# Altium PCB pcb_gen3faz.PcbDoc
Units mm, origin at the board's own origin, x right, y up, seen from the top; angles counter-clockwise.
Board outline 69.09 x 22.1 mm, 2 copper layers (Top Layer, Bottom Layer); 24 components, 18 nets, 67 pads, 0 vias.
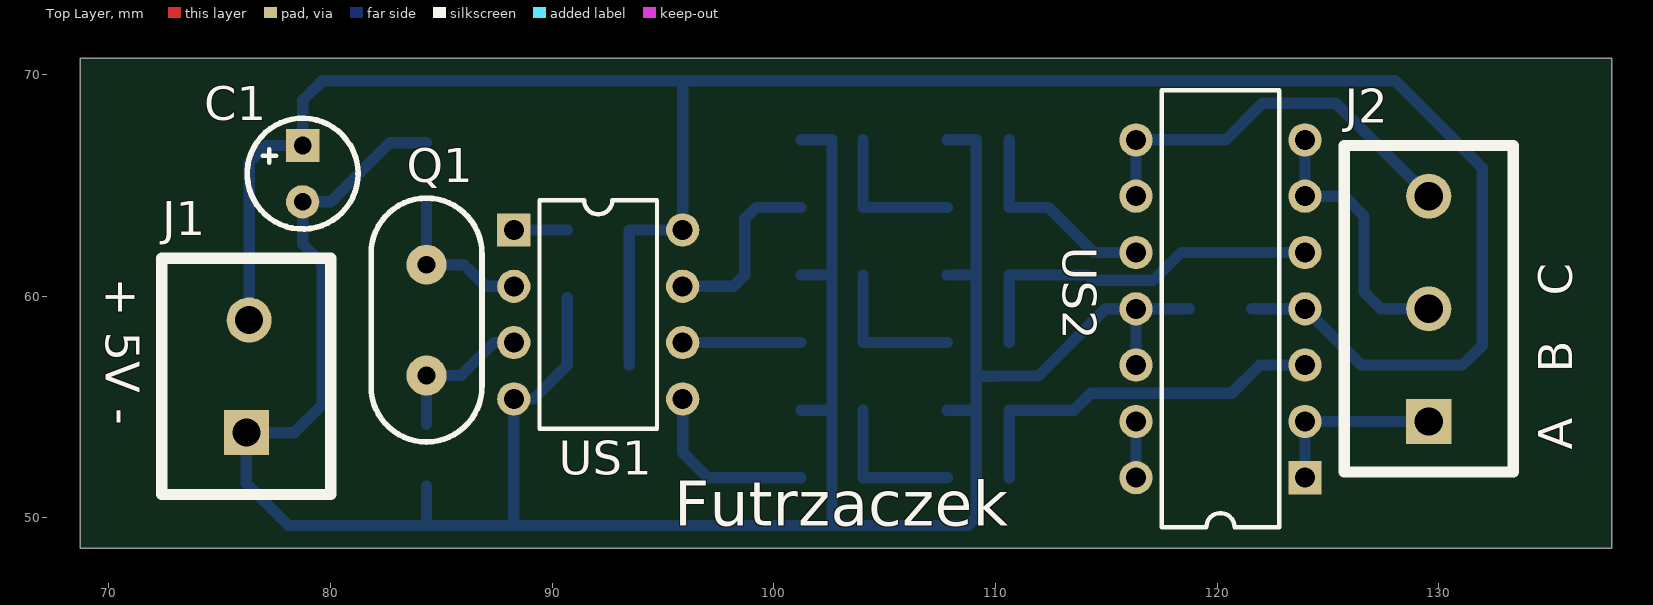
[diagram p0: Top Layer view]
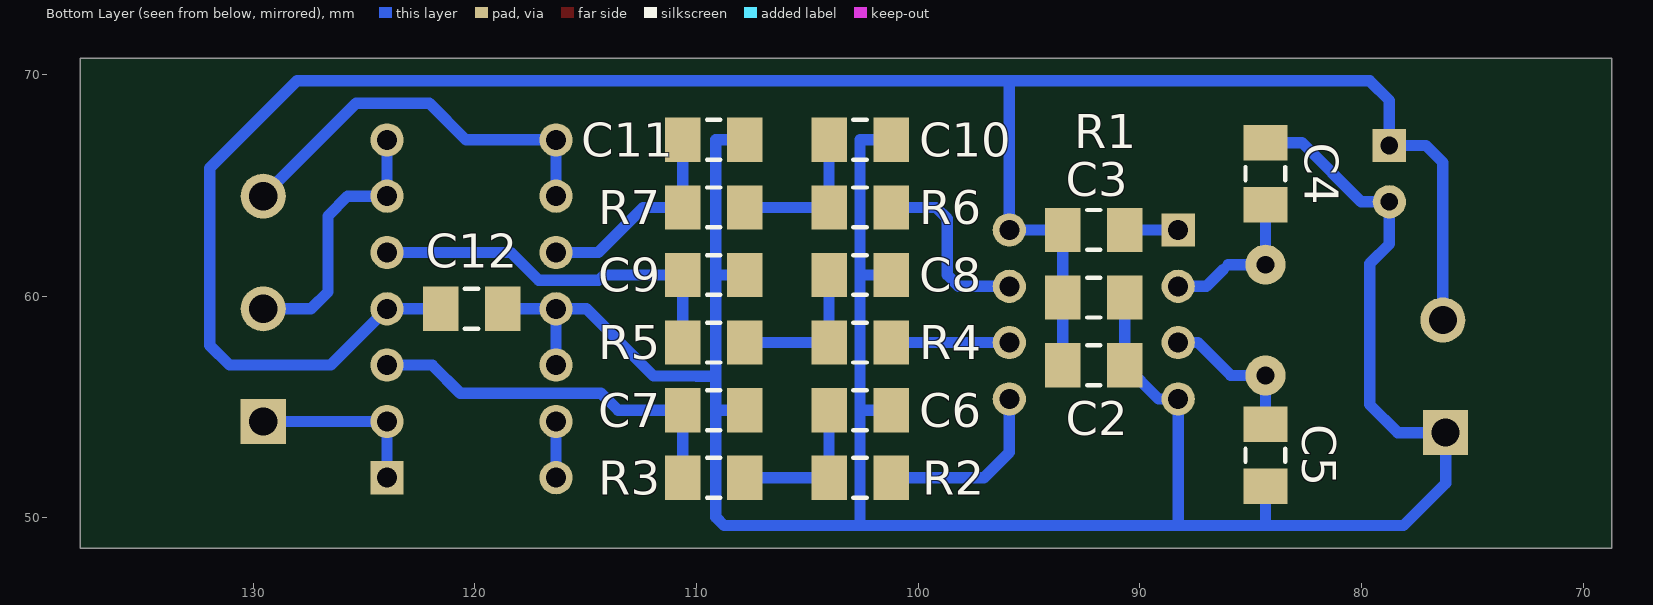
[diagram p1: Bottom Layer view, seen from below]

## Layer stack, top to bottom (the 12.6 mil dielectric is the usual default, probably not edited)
Top Layer: signal copper 0.0356
Dielectric: dielectric 0.32, FR-4, Dk 4.8
Bottom Layer: signal copper 0.0356

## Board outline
68.707,48.641 68.707,70.739 137.795,70.739 137.795,48.641

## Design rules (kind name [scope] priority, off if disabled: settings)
Clearance [All] p1: gap=0.254
PolygonConnect [All] p1: connectstyle=Relief reliefconductorwidth=0.254 reliefentries=4 polygonreliefangle="90 Angle"
RoutingVias [All] p1: holewidth=0.8 width=1.5 viastyle="Through Hole" minholewidth=0.8 minwidth=1.5 maxholewidth=0.8 maxwidth=1.5
SilkscreenOverComponentPads [All] p1: minsilkscreentomaskgap=0.254
SolderMaskExpansion [All] p1: expansion=0.102
Width [All] p1: maxlimit=2.54 minlimit=0.254 preferedwidth=0.508
27 further rules are at their usual default settings.

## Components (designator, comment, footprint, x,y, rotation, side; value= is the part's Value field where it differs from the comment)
C1 "100u/16V" "2,5/5mm elektrolit" 78.74,65.532 r270 top
C2 "470p" MELF-1206 92.075,56.896 r0 bottom
C3 "100n" MELF-1206 92.075,59.944 r0 bottom
C4 "18p" MELF-1206 84.328,65.532 r270 bottom
C5 "18p" MELF-1206 84.328,52.832 r90 bottom
C6 "100n" MELF-1206 102.616,54.864 r0 bottom
C7 "100n" MELF-1206 109.22,54.864 r0 bottom
C8 "100n" MELF-1206 102.616,60.96 r0 bottom
C9 "100n" MELF-1206 109.22,60.96 r0 bottom
C10 "100n" MELF-1206 102.616,67.056 r0 bottom
C11 "100n" MELF-1206 109.22,67.056 r0 bottom
C12 "100n" MELF-1206 120.142,59.436 r0 bottom
J1 "ARK2" "ARK2 5mm" 76.2,56.388 r90 top
J2 "ARK3" "ARK3 5mm" 129.54,59.436 r90 top
Q1 "16MHz" "kwarc 5mm" 84.328,58.928 r90 top
R1 "4,7k" MELF-1206 92.075,62.992 r0 bottom
R2 "4,7k" MELF-1206 102.616,51.816 r180 bottom
R3 "33k" MELF-1206 109.22,51.816 r180 bottom
R4 "4,7k" MELF-1206 102.616,57.912 r180 bottom
R5 "33k" MELF-1206 109.22,57.912 r180 bottom
R6 "4,7k" MELF-1206 102.616,64.008 r180 bottom
R7 "33k" MELF-1206 109.22,64.008 r180 bottom
US1 "ATtiny25" 8P3 92.075,59.182 r270 top
US2 "LM324" N014 120.142,59.436 r90 top

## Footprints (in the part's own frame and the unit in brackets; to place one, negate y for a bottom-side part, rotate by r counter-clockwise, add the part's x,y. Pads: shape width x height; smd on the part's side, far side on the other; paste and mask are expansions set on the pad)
"2,5/5mm elektrolit" [mm]
  rect 1.5x1.5 hole 0.8: 1(-1.27,0)
  round 1.5 hole 0.8: 2(1.27,0)
  silkscreen extent -2.5,-2.5 2.5,2.5, body extent -2.51,-2.51 2.51,2.51
8P3 [mm] "DIP; 8 Leads; Row Spacing 7.62 mm; Pitch 2.54 mm"
  rect 1.5x1.5 hole 0.9: 1(-3.81,-3.81)
  round 1.5 hole 0.9: 2(-1.27,-3.81) 3(1.27,-3.81) 4(3.81,-3.81) 5(3.81,3.81) 6(1.27,3.81) 7(-1.27,3.81) 8(-3.81,3.81)
  silkscreen extent -5.15,-2.65 5.15,2.65
"ARK2 5mm" [mil]
  rect 80x80 hole 50: 1(-100,0)
  round 80 hole 50: 2(100,-5)
  silkscreen extent -210,-150 210,150, body extent -220,-160 220,160, height 394
"ARK3 5mm" [mil]
  rect 80x80 hole 50: 1(-200,0)
  round 80 hole 50: 2(0,0) 3(200,0)
  silkscreen extent -290,-150 290,150, body extent -300,-160 300,160, height 394
"kwarc 5mm" [mm]
  round 1.8 hole 0.8: 1(-2.5,0) 2(2.5,0)
  silkscreen extent -5.5,-2.5 5.5,2.5
MELF-1206 [mm] "Metal Electrode Face (MELF) Resistor; Body 3.2 x 1.8 mm (LxDia)"
  rect 1.6x2 smd: 1(-1.4,0) 2(1.4,0)
  silkscreen extent -0.3,-0.9 0.3,0.9, body extent -2.3,-1.1 2.3,1.1, height 1.85
N014 [mm] "DIP; 14 Leads; Row Spacing 7.62 mm; Pitch 2.54 mm"
  rect 1.5x1.5 hole 0.9: 1(-7.62,-3.81)
  round 1.5 hole 0.9: 2(-5.08,-3.81) 3(-2.54,-3.81) 4(0,-3.81) 5(2.54,-3.81) 6(5.08,-3.81) 7(7.62,-3.81) 8(7.62,3.81) 9(5.08,3.81) 10(2.54,3.81) 11(0,3.81) 12(-2.54,3.81) 13(-5.08,3.81) 14(-7.62,3.81)
  silkscreen extent -9.85,-2.65 9.85,2.65

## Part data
C1: library part "kond biegunowy", "Polarized Capacitor"
C2 C3 C4 C5 C6 C7 C8 C9 C10 C11 C12: library part kondensator
Q1: library part kwarc
R1 R2 R3 R4 R5 R6 R7: library part rezystor
US1: library part ATtiny12V-1PI, "8-Bit AVR Microcontroller with 1K Byte of Flash Memory"
US2: library part LM324AN, "Quadruple Operational Amplifier"

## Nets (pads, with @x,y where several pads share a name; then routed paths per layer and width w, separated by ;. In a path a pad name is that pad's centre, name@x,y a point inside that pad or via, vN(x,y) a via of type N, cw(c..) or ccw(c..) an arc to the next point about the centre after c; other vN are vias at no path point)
+5V: C1.1 C2.2 C3.2 C12.2 J1.2 R1.2 US1.8 US2.4 | length 102.7
  Bottom Layer w0.508: J1.2 76.327,66.04 77.089,66.802 C1.1 78.74,68.834 79.629,69.723 95.885,69.723 ; C2.2 C3.2 R1.2 US1.8 ; US1.8@95.377,62.992 US1.8 ; C12.2 US2.4 126.492,56.896 131.064,56.896 131.953,57.785 131.953,65.786 128.016,69.723 95.885,69.723 ; US1.8 95.885,69.723
GND: C1.2 C2.1 C3.1 C4.1 C5.1 C6.1 C7.1 C8.1 C9.1 C10.1 C11.1 C12.1 J1.1 US1.4 US2.11 US2.12 | length 126.6
  Bottom Layer w0.508: 84.328,49.784 C5.1 ; C4.1 82.68,66.932 80.01,64.262 C1.2 78.74,62.357 79.629,61.468 79.629,55.118 78.359,53.848 J1.1 76.2,51.562 78.105,49.657 88.265,49.657 ; C3.1 C2.1 89.151,55.372 US1.4 88.265,49.657 ; C6.1 102.616,54.864 ; C8.1 102.616,60.96 ; C10.1 102.616,67.056 102.616,60.96 ; 102.616,49.657 101.6,49.657 ; 102.616,49.784 102.616,54.864 ; C7.1 109.128,54.864 ; C9.1 109.128,60.96 ; C11.1 109.128,67.056 109.128,60.96 ; US2.12 US2.11 ; C12.1 US2.11 ; 88.265,49.657 101.6,49.657 ; 101.6,49.657 108.747,49.657 109.128,50.038 109.128,54.864 ; 102.616,54.864 102.616,60.96 ; 109.128,54.864 109.128,56.388 ; 109.128,56.388 109.128,60.96 ; 109.128,56.388 109.982,56.388 109.998,56.404 111.928,56.404 114.96,59.436 US2.11
NetC6_2: C6.2 R2.1 R3.2 | length 6.9
  Bottom Layer w0.508: C6.2 R2.1 R3.2
NetC7_2: C7.2 R3.1 US2.3 | length 17.2
  Bottom Layer w0.508: R3.1 C7.2 113.538,54.864 114.3,55.626 120.65,55.626 121.92,56.896 US2.3
NetC8_2: C8.2 R4.1 R5.2 | length 6.9
  Bottom Layer w0.508: C8.2 R4.1 R5.2
NetC9_2: C9.2 R5.1 US2.5 | length 17
  Bottom Layer w0.508: R5.1 C9.2 114.173,60.96 114.415,60.718 117.106,60.718 117.348,60.96 118.364,61.976 US2.5
NetC10_2: C10.2 R6.1 R7.2 | length 6.9
  Bottom Layer w0.508: C10.2 R6.1 R7.2
NetC11_2: C11.2 R7.1 US2.10 | length 9.6
  Bottom Layer w0.508: C11.2 R7.1 112.395,64.008 114.427,61.976 US2.10
NetJ2_1: J2.1 US2.1 US2.2 | length 8.1
  Bottom Layer w0.508: US2.1 US2.2 J2.1
NetJ2_2: J2.2 US2.6 US2.7 | length 12.2
  Bottom Layer w0.508: US2.7 US2.6 125.73,64.516 126.619,63.627 126.619,60.198 127.381,59.436 J2.2
NetJ2_3: J2.3 US2.8 US2.9 | length 18.2
  Bottom Layer w0.508: US2.9 US2.8 120.396,67.056 122.047,68.707 125.349,68.707 J2.3
NetR1_1: R1.1 US1.1 | length 2.4
  Bottom Layer w0.508: US1.1 R1.1
NetUS2_13: US2.13 US2.14 | length 2.5
  Bottom Layer w0.508: US2.14 US2.13
PWM1: R2.2 US1.5 | length 8.2
  Bottom Layer w0.508: US1.5 95.885,52.959 97.028,51.816 R2.2
PWM2: R4.2 US1.6 | length 5.3
  Bottom Layer w0.508: US1.6 R4.2
PWM3: R6.2 US1.7 | length 8.3
  Bottom Layer w0.508: US1.7 98.171,60.452 98.679,60.96 98.679,63.5 99.187,64.008 R6.2
XTAL1: C4.2 Q1.2 US1.2 | length 6.7
  Bottom Layer w0.508: C4.2 Q1.2 86.019,61.428 ; 86.233,61.214 86.995,60.452 US1.2
XTAL2: C5.2 Q1.1 US1.3 | length 6.7
  Bottom Layer w0.508: C5.2 Q1.1 85.892,56.428 87.376,57.912 US1.3

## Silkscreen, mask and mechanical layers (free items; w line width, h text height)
Top Overlay:
  text "+ 5V -" at 69.85,60.833 h1.52 r270
  text "A   B   C" at 136.017,53.086 h1.52 r90
  text "Futrzaczek" at 95.504,49.657 h2.03
Mechanical 1:
  the board outline again, w0.254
